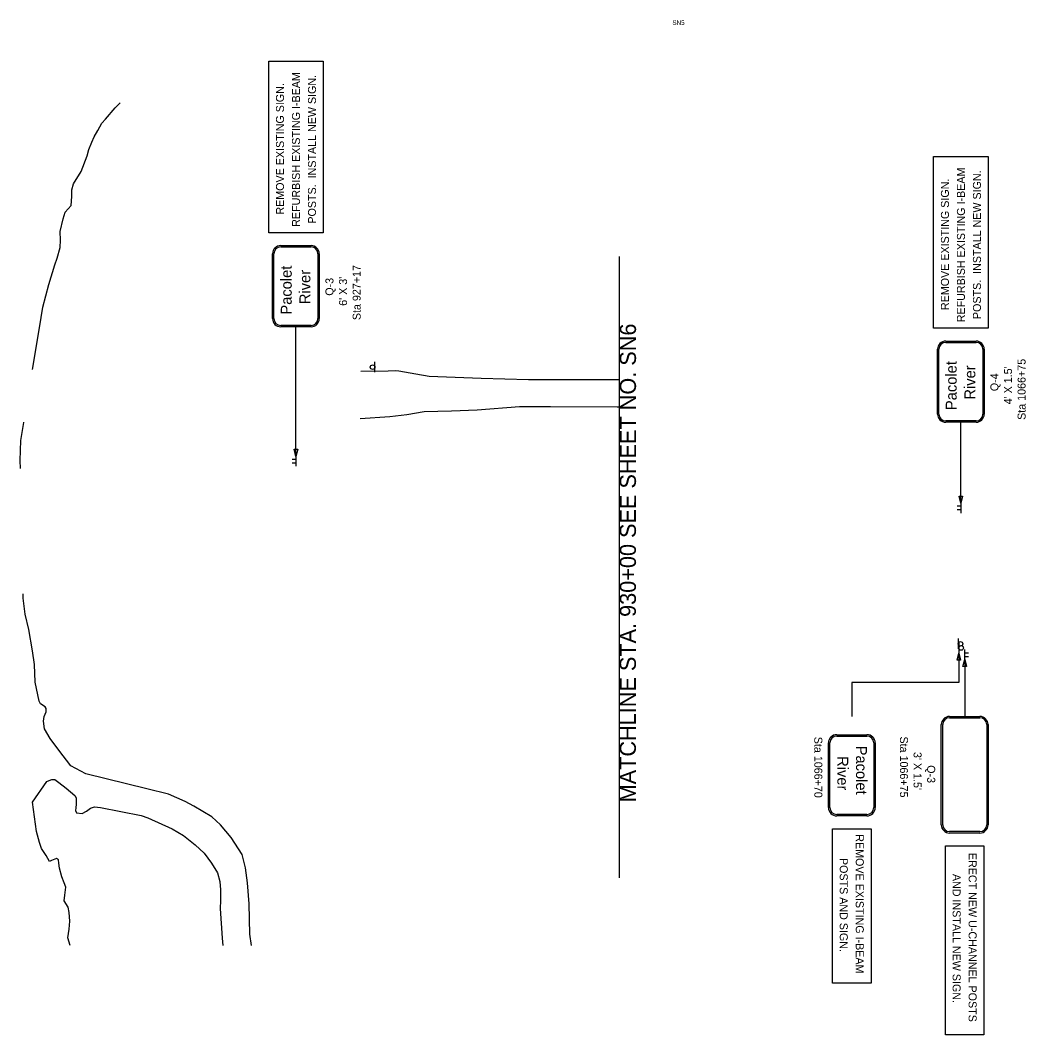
# Model space of a CAD drawing. Extents: x 1738774 to 1740659, y 1167903 to 1168804.
# Drawn here: x 1739780 to 1740659, y 1167903 to 1168790 of the extents above; entities that cross this region are included whole.
import ezdxf

# ---------------------------------------------------------------- set-up
doc = ezdxf.new("R2010")
doc.units = 0
for name, color, linetype in [('RD_EX_H2O', 7, 'Continuous'), ('RD_EX_Road', 7, 'Continuous'), ('RD_SHT_MatchLine', 7, 'Continuous'), ('RD_SHT_TX', 7, 'Continuous'), ('SN_P_Signs', 7, 'Continuous')]:
    doc.layers.add(name, color=color, linetype=linetype)

msp = doc.modelspace()

# ---------------------------------------------------------------- linework, layer by layer
at = {"layer": 'RD_EX_H2O'}
for points in [[(1739790.48, 1168484.66), (1739796.51, 1168521.01), (1739799.28, 1168539.16), (1739804.67, 1168558.93), (1739809.99, 1168576.18), (1739811.91, 1168581.99), (1739814.69, 1168591.32), (1739814.76, 1168597.77), (1739814.51, 1168605.46), (1739817.24, 1168616.47), (1739819.01, 1168622.42), (1739824.15, 1168628.18), (1739824.74, 1168636.05), (1739824.83, 1168641.8), (1739826.34, 1168647.03), (1739833, 1168657.89), (1739838.3, 1168671.66), (1739839.67, 1168677.17), (1739842.12, 1168683.55), (1739844.36, 1168688.11), (1739847.54, 1168693.82), (1739851.13, 1168699.96), (1739854.09, 1168703.56), (1739862.6, 1168713.65), (1739866.99, 1168717.77)], [(1739779.82, 1168398.16), (1739779.67, 1168405.02), (1739780.23, 1168422.52), (1739782.8, 1168438.27), (1739782.84, 1168438.52)], [(1739981.97, 1167980.98), (1739980.53, 1167990.96), (1739979.77, 1168017.59), (1739978.27, 1168035.85), (1739976.7, 1168049.09), (1739973.76, 1168060.5), (1739964.07, 1168075.45), (1739954.84, 1168086.5), (1739947.2, 1168093.67), (1739931.57, 1168102.97), (1739923.96, 1168107.07), (1739909.33, 1168113.31), (1739890.38, 1168117.97), (1739837.06, 1168131.19), (1739823.99, 1168138.3), (1739813.36, 1168151.92), (1739805.78, 1168162.01), (1739800.9, 1168170.51), (1739799.99, 1168177.18), (1739800.55, 1168181.24), (1739802.37, 1168185.49), (1739802.42, 1168188.43), (1739801.4, 1168189.79), (1739797.4, 1168192.45), (1739796.07, 1168194.78), (1739792.75, 1168211.3), (1739792.11, 1168226.78), (1739790.47, 1168238.6), (1739787.07, 1168257.49), (1739783.99, 1168270.8), (1739782.28, 1168284.86), (1739782.31, 1168288.08), (1739782.3, 1168288.42)], [(1739823.28, 1167980.98), (1739821.39, 1167987.64), (1739822.53, 1167995.34), (1739823, 1168002.47), (1739822.34, 1168009.98), (1739821.49, 1168014.7), (1739818.11, 1168020.17), (1739818.51, 1168025.07), (1739819.4, 1168031.93), (1739818.02, 1168035.93), (1739816.04, 1168041.03), (1739813.98, 1168048.78), (1739813.29, 1168052.94), (1739813.05, 1168055.87), (1739811.47, 1168057.21), (1739807.07, 1168055.4), (1739805.14, 1168054.64), (1739802.32, 1168059.85), (1739798.35, 1168066), (1739796.51, 1168071.24), (1739793.97, 1168080.65), (1739790.49, 1168106.37), (1739803.03, 1168124.36), (1739804.95, 1168125.4), (1739807.16, 1168126.3), (1739809.95, 1168126.11), (1739813.38, 1168123.57), (1739819.68, 1168118.75), (1739827.28, 1168112.16), (1739828.46, 1168110.25), (1739828.64, 1168104.67), (1739828.19, 1168101.45), (1739827.98, 1168099.07), (1739828.88, 1168097.15), (1739833.65, 1168096.46), (1739837.63, 1168098.54), (1739841.03, 1168101.16), (1739844.48, 1168102.25), (1739849.94, 1168101.73), (1739885.32, 1168094.64), (1739891.13, 1168092.79), (1739912.38, 1168083.14), (1739922.39, 1168077.25), (1739932.56, 1168069.14), (1739940.62, 1168061.69), (1739947.02, 1168052.98), (1739952.02, 1168044.66), (1739954.21, 1168037.15), (1739954.73, 1168029.76), (1739954.85, 1168020.54), (1739954.53, 1168013.28), (1739956.26, 1167987.48), (1739956.8, 1167980.98)]]:
    msp.add_lwpolyline(points, dxfattribs=at)
at = {"layer": 'RD_EX_Road'}
for points in [[(1740303.73, 1168475.65), (1740276.57, 1168475.65), (1740224.12, 1168475.54), (1740182.78, 1168476.89), (1740137.43, 1168478.57), (1740125.74, 1168480.75), (1740110.91, 1168483.23), (1740107.64, 1168483.52), (1740101.57, 1168483.31), (1740077.39, 1168483.08)], [(1740303.73, 1168451.8), (1740301.64, 1168451.79), (1740243.54, 1168452.03), (1740216.29, 1168452.01), (1740179.41, 1168449.16), (1740156.73, 1168448.27), (1740132.89, 1168447.7), (1740117.8, 1168445.04), (1740102.76, 1168443.18), (1740077.08, 1168441.48)]]:
    msp.add_lwpolyline(points, dxfattribs=at)
at = {"layer": 'RD_SHT_MatchLine'}
msp.add_lwpolyline([(1740303.73, 1168040.3), (1740303.73, 1168344.04), (1740303.73, 1168583.44)], dxfattribs=at)
at = {"layer": 'SN_P_Signs'}
for p, q in [((1739996.95, 1168604.31), (1739996.95, 1168754.33)), ((1739996.95, 1168754.33), (1740044.57, 1168754.33)), ((1740044.57, 1168754.33), (1740044.57, 1168604.31)), ((1740578.55, 1168520.85), (1740578.55, 1168670.87)), ((1740578.55, 1168670.87), (1740626.16, 1168670.87)), ((1740626.16, 1168670.87), (1740626.16, 1168520.85)), ((1740044.57, 1168604.31), (1739996.95, 1168604.31)), ((1740000.33, 1168529.24), (1740000.33, 1168585.85)), ((1740020.76, 1168408.76), (1740020.76, 1168522.04)), ((1740626.16, 1168520.85), (1740578.55, 1168520.85)), ((1740581.92, 1168445.78), (1740581.92, 1168502.39)), ((1740089.9, 1168482.28), (1740089.79, 1168491.28)), ((1740602.36, 1168367.9), (1740602.36, 1168438.58)), ((1740020.76, 1168408.76), (1740020.76, 1168400.06)), ((1740020.76, 1168406.15), (1740017.44, 1168406.15)), ((1740020.76, 1168402.81), (1740017.44, 1168402.81)), ((1740602.36, 1168365.29), (1740599.03, 1168365.29)), ((1740602.36, 1168367.9), (1740602.36, 1168359.2)), ((1740602.36, 1168361.95), (1740599.03, 1168361.95)), ((1740599.91, 1168249.36), (1740599.97, 1168240.36)), ((1740600.52, 1168245.75), (1740600.58, 1168236.75)), ((1740605.68, 1168231.15), (1740605.68, 1168239.85)), ((1740600.58, 1168236.75), (1740600.58, 1168210.92)), ((1740605.68, 1168237.11), (1740609.01, 1168237.11)), ((1740605.68, 1168233.76), (1740609.01, 1168233.76)), ((1740605.68, 1168231.15), (1740605.68, 1168181.4)), ((1740506.96, 1168210.92), (1740506.96, 1168181.4)), ((1740600.58, 1168210.92), (1740506.96, 1168210.92)), ((1740626.12, 1168174.2), (1740626.12, 1168086.6)), ((1740527.4, 1168158.2), (1740527.4, 1168101.59)), ((1740490.15, 1167948.04), (1740490.15, 1168083.06)), ((1740490.15, 1168083.06), (1740523.77, 1168083.06)), ((1740523.77, 1168083.06), (1740523.77, 1167948.04)), ((1740588.87, 1167903.06), (1740588.87, 1168068.08)), ((1740588.87, 1168068.08), (1740622.49, 1168068.08)), ((1740622.49, 1168068.08), (1740622.49, 1167903.06)), ((1740523.77, 1167948.04), (1740490.15, 1167948.04)), ((1740622.49, 1167903.06), (1740588.87, 1167903.06))]:
    msp.add_line(p, q, dxfattribs=at)
for points in [[(1740001.53, 1168529.24), (1740001.53, 1168585.85)], [(1740007.53, 1168593.05), (1740034, 1168593.05)], [(1740007.53, 1168591.85), (1740034, 1168591.85)], [(1740040, 1168585.85), (1740040, 1168529.24)], [(1740041.2, 1168585.85), (1740041.2, 1168529.24)], [(1740034, 1168523.24), (1740007.53, 1168523.24)], [(1740034, 1168522.04), (1740007.53, 1168522.04)], [(1740589.12, 1168509.59), (1740615.59, 1168509.59)], [(1740589.12, 1168508.39), (1740615.59, 1168508.39)], [(1740583.12, 1168445.78), (1740583.12, 1168502.39)], [(1740621.59, 1168502.39), (1740621.59, 1168445.78)], [(1740622.79, 1168502.39), (1740622.79, 1168445.78)], [(1740615.59, 1168439.78), (1740589.12, 1168439.78)], [(1740615.59, 1168438.58), (1740589.12, 1168438.58)], [(1740592.45, 1168181.4), (1740618.92, 1168181.4)], [(1740592.45, 1168180.2), (1740618.92, 1168180.2)], [(1740585.25, 1168086.6), (1740585.25, 1168174.2)], [(1740586.45, 1168086.6), (1740586.45, 1168174.2)], [(1740624.92, 1168174.2), (1740624.92, 1168086.6)], [(1740493.73, 1168165.4), (1740520.2, 1168165.4)], [(1740493.73, 1168164.2), (1740520.2, 1168164.2)], [(1740486.53, 1168101.59), (1740486.53, 1168158.2)], [(1740487.73, 1168101.59), (1740487.73, 1168158.2)], [(1740526.2, 1168158.2), (1740526.2, 1168101.59)], [(1740520.2, 1168095.59), (1740493.73, 1168095.59)], [(1740520.2, 1168094.39), (1740493.73, 1168094.39)], [(1740618.92, 1168080.6), (1740592.45, 1168080.6)], [(1740618.92, 1168079.4), (1740592.45, 1168079.4)]]:
    msp.add_lwpolyline(points, dxfattribs=at)
for points in [[(1740022.3, 1168414.91), (1740020.76, 1168408.76), (1740019.22, 1168414.91)], [(1740603.89, 1168374.05), (1740602.36, 1168367.9), (1740600.82, 1168374.05)], [(1740599.04, 1168230.6), (1740600.58, 1168236.75), (1740602.12, 1168230.6)], [(1740604.14, 1168225), (1740605.68, 1168231.15), (1740607.22, 1168225)]]:
    msp.add_lwpolyline(points, close=True, dxfattribs=at)
for centre in [(1740087.82, 1168486.77), (1740601.97, 1168244.86), (1740602.57, 1168241.24)]:
    msp.add_circle(centre, 2, dxfattribs=at)
for centre, radius, start, end in [((1740007.53, 1168585.85), 7.2, 90, 180), ((1740007.53, 1168585.85), 6, 90, 180), ((1740034, 1168585.85), 7.2, 0, 90), ((1740034, 1168585.85), 6, 0, 90), ((1740007.53, 1168529.24), 7.2, 180, 270), ((1740007.53, 1168529.24), 6, 180, 270), ((1740034, 1168529.24), 6, 270, 0), ((1740034, 1168529.24), 7.2, 270, 0), ((1740589.12, 1168502.39), 7.2, 90, 180), ((1740589.12, 1168502.39), 6, 90, 180), ((1740615.59, 1168502.39), 7.2, 0, 90), ((1740615.59, 1168502.39), 6, 0, 90), ((1740589.12, 1168445.78), 7.2, 180, 270), ((1740589.12, 1168445.78), 6, 180, 270), ((1740615.59, 1168445.78), 6, 270, 0), ((1740615.59, 1168445.78), 7.2, 270, 0), ((1740592.45, 1168174.2), 7.2, 90, 180), ((1740592.45, 1168174.2), 6, 90, 180), ((1740618.92, 1168174.2), 7.2, 0, 90), ((1740618.92, 1168174.2), 6, 0, 90), ((1740493.73, 1168158.2), 7.2, 90, 180), ((1740493.73, 1168158.2), 6, 90, 180), ((1740520.2, 1168158.2), 7.2, 0, 90), ((1740520.2, 1168158.2), 6, 0, 90), ((1740493.73, 1168101.59), 7.2, 180, 270), ((1740493.73, 1168101.59), 6, 180, 270), ((1740520.2, 1168101.59), 6, 270, 0), ((1740520.2, 1168101.59), 7.2, 270, 0), ((1740592.45, 1168086.6), 7.2, 180, 270), ((1740592.45, 1168086.6), 6, 180, 270), ((1740618.92, 1168086.6), 6, 270, 0), ((1740618.92, 1168086.6), 7.2, 270, 0)]:
    msp.add_arc(centre, radius, start, end, dxfattribs=at)

# ---------------------------------------------------------------- texts
at = {"layer": 'RD_SHT_TX'}
msp.add_text('SN5', height=4, dxfattribs=at).set_placement((1740350.02, 1168786))
msp.add_text('MATCHLINE STA. 930+00 SEE SHEET NO. SN6', height=14.1726, rotation=89.98556, dxfattribs=at).set_placement((1740318.1, 1168106.21))
at = {"layer": 'SN_P_Signs'}
for s, height, rotation, p in [('REFURBISH EXISTING I-BEAM', 6.9998, 90.00008, (1740024.32, 1168609.49)), ('POSTS.  INSTALL NEW SIGN.', 6.9998, 90.00008, (1740038.32, 1168612.27)), ('REMOVE EXISTING SIGN.', 6.9998, 90.00008, (1740010.32, 1168620.15)), ('REFURBISH EXISTING I-BEAM', 6.9998, 90.00008, (1740605.91, 1168526.03)), ('POSTS.  INSTALL NEW SIGN.', 6.9998, 90.00008, (1740619.91, 1168528.81)), ('REMOVE EXISTING SIGN.', 6.9998, 90.00008, (1740591.91, 1168536.68)), ('Pacolet', 9.6, 90, (1740017.08, 1168532.69)), ('River', 9.6, 90, (1740033.4, 1168541.83)), ('Sta 927+17', 7, 90.00008, (1740077.37, 1168527.89)), ('Q-3', 7, 90.00008, (1740053.57, 1168549.22)), ("6' X 3'", 7, 90.00008, (1740065.47, 1168540.4)), ('Pacolet', 9.6, 90, (1740598.67, 1168449.23)), ('Sta 1066+75', 7, 90.00008, (1740658.96, 1168440.68)), ('River', 9.6, 90, (1740614.99, 1168458.37)), ('Q-4', 7, 90.00008, (1740635.16, 1168465.76)), ("4' X 1.5'", 7, 90.00008, (1740647.06, 1168454.24)), ('Sta 1066+70', 7, 270.00008, (1740474.16, 1168163.57)), ('Sta 1066+75', 7, 270.00008, (1740549.08, 1168163.81)), ('Pacolet', 9.6, 270, (1740510.65, 1168155.78)), ('River', 9.6, 270, (1740494.33, 1168146.63)), ("3' X 1.5'", 7, 270.00008, (1740560.98, 1168150.25)), ('Q-3', 7, 270.00008, (1740572.88, 1168138.73)), ('REMOVE EXISTING I-BEAM', 6.9998, 270.00008, (1740510.41, 1168078.32)), ('POSTS AND SIGN.', 6.9998, 270.00008, (1740496.41, 1168057.61)), ('ERECT NEW U-CHANNEL POSTS', 6.9998, 270.00008, (1740609.13, 1168062.03)), ('AND INSTALL NEW SIGN.', 6.9998, 270.00008, (1740595.13, 1168043.65))]:
    msp.add_text(s, height=height, rotation=rotation, dxfattribs=at).set_placement(p)

doc.saveas('drawing.dxf')
